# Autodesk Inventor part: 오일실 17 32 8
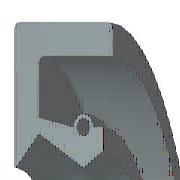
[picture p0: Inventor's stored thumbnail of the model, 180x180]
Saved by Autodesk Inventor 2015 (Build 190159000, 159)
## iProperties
IsCustomPart: 1
Created: 2012-02
Part Number: 오일실 17 32 8
Material: 고무
Description: 오일-실
Document SubType Name: Modeling
Standard: KS B 2804
Designer: mduedu
Standards Organization: KS
Language: ko-KR
Size Designation: D - 17 32 8
Categories: <MemberInstance><Categories><Category DisplayName="샤프트 부품" InternalName="7f7aeb1f-a693-4053-b835-cee3144e0d98" Mnemonic="SHFT"><Category DisplayName="실링" Intern
Density: 0.93 g/cm^3
Appearance: Rubber - Black - Version 1.1
Author: mduedu
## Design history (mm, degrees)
revolve "본체" stored, may be unused: angle "d17" = 90 deg
revolve "스프링1" stored, may be unused: angle "d18" = 90 deg
body "Solid1"
sketch "스케치1"
  geometry: L1 (0, 16)-(8, 16); L2 (8, 14.25)-(1.75, 14.25); L3 (1.75, 10.25)-(4.9, 8.5); L4 (4.9, 8.5)-(0, 8.5); L5 (0, 0)-(9.586, 0) reference; L6 (4.9, 8.5)-(6.3, 9.375); L7 (0, 18)-(0, -3) reference; L8 (-1.941, 0)-(11.507, 0) reference; L9 (4.2, 10.6)-(1.75, 11.21); L10 (1.75, 11.21)-(1.75, 14.25); L11 (0, 16)-(0, 8.588); L12 (4.9, 8.5)-(0, 8.5); L13 (1.75, 10.25)-(0.152, 8.528); L14 (8, 16)-(8, 14.25); L15 (5.6, 10.6)-(6.3, 10.6); L16 (6.3, 10.6)-(6.3, 9.375); C1 r 0.455 at (4.9, 10.6); A1 r 0.7 centre (4.9, 10.6) between (5.6, 10.6) and (4.2, 10.6); A2 r 0.088 centre (0.088, 8.588) between (0, 8.588) and (0.152, 8.528); 1 further point
  constraints: 28 end point, 5 horizontal alignment, 5 point on line, 4 point on circle, 4 vertical alignment, 3 centre point, 3 tangent, 2 collinear, 2 horizontal, 2 perpendicular, 1 coincident, 1 parallel
  dimensions: "d0" = 32 diameter of L1 L5 (= SD2); "d1" = 1.75 distance of L1.end L2.start (= SD); "d2" = 0.91 diameter of C1 (= SPDI); "d3" = 1.4 diameter of A1 (= SPDA); "d4" = 17 diameter of L3.end L5 (= NND); "d5" = 20.5 diameter of L3.start L5 (= TKDM); "d7" = 22.42 diameter of L9.end L5 (= TKDM + 0.24 x SWDT); "d8" = 1.75 distance between parallel lines of L11 L10 (= SD); "d9" = 4.9 distance from line of L11 C1.centre (= SPDST); "d10" = 21.2 diameter of C1.centre L5 (= HLDM); "d11" = 0.0875 radius of A2 (= 0.25 x LAB); "d12" = 6.3 distance between parallel lines of L11 L16 (= SDI); "d13" = 18.75 diameter of L6.end L5 (= ABDM); "d14" = 8 distance from line of L11 L1.end (= SWDT)
fillet "모깎기1" dims "d6" = 0.3 (= RR)
other parameters: "SD2" = 32 [user parameter; used in 1 equation term], "SWDT" = 8 [user parameter; used in 2 equation terms], "RR" = 0.3 [user parameter; used in 1 equation term], "SD" = 1.75 [user parameter; used in 2 equation terms], "NND" = 17 [user parameter; used in 1 equation term], "SPDA" = 1.4 [user parameter; used in 1 equation term], "SPDI" = 0.91 [user parameter; used in 1 equation term], "TKDM" = 20.5 [user parameter; used in 2 equation terms], "HLDM" = 21.2 [user parameter; used in 1 equation term], "ABDM" = 18.75 [user parameter; used in 1 equation term], "SDI" = 6.3 [user parameter; used in 1 equation term], "SPDST" = 4.9 [user parameter; used in 1 equation term], "LAB" = 0.35 [user parameter; used in 1 equation term], "d15" = 0, "d16" = 0, "d19" = 0
